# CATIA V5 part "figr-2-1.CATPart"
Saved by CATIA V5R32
Part number: figr-2-1
Bounding box of the stored display mesh (mm): x 0 to 10, y -99.811 to 99.811, z -49.833 to 49.833
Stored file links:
  D:\PROJECTS\Project 2022\CATIA V5 6R 2022\Resources\Part Files\c02_catia_v5_6r2022_prt\figr-2-1.CATPart
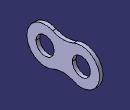
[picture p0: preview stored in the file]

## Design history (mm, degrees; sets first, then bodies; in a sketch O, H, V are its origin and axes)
Body1 (main body)
  Sketch1 on yz-plane, origin (0, 0, 0), H (0, 1, 0), V (0, 0, 1)
    arc A1 centre (50, 0) radius 50 from (29.1667, -45.453) to (29.1666, 45.4529) ccw
    point P1 (50, 0)
    arc A2 centre (-50, 0) radius 50 from (-29.1666, 45.4529) to (-29.1667, -45.453) ccw
    point P2 (-50, 0)
    arc A3 centre (0, 109.0871) radius 70 from (-29.1666, 45.4529) to (29.1667, 45.453) ccw
    point P4 (-29.1666, 45.4529)
    point P5 (0, 39.0871)
    point P6 (29.1667, 45.453)
    point P7 (29.1667, -45.453)
    point P8 (-29.1666, -45.4529)
    arc A4 centre (0, -109.0871) radius 70 from (-29.1666, -45.4529) to (29.1667, -45.453) cw
    point P10 (-29.1667, -45.453)
    point P11 (-29.1666, 45.4529)
    point P12 (29.1666, 45.4529)
    point P13 (29.1667, -45.453)
    circle A5 centre (50, 0) radius 25
    circle A6 centre (-50, 0) radius 25
    distance P1 P2 = 100
    radius A1 = 50
    radius A2 = 50
    distance O P2 = 50
    radius A5 = 25
    radius A6 = 25
    radius A3 = 70
    coincidence: P1 H, P2 H, P4 A2, A3 P5, P5 V, P6 A1, A4 P10, A3 P11, A3 P12, A4 P13
    tangency: A3 A1, A3 A2
    symmetry: P6 P7 H, P4 P8 H, A3 A4 H
  Pad1: profile Sketch1, direction (1, 0, 0), length 10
